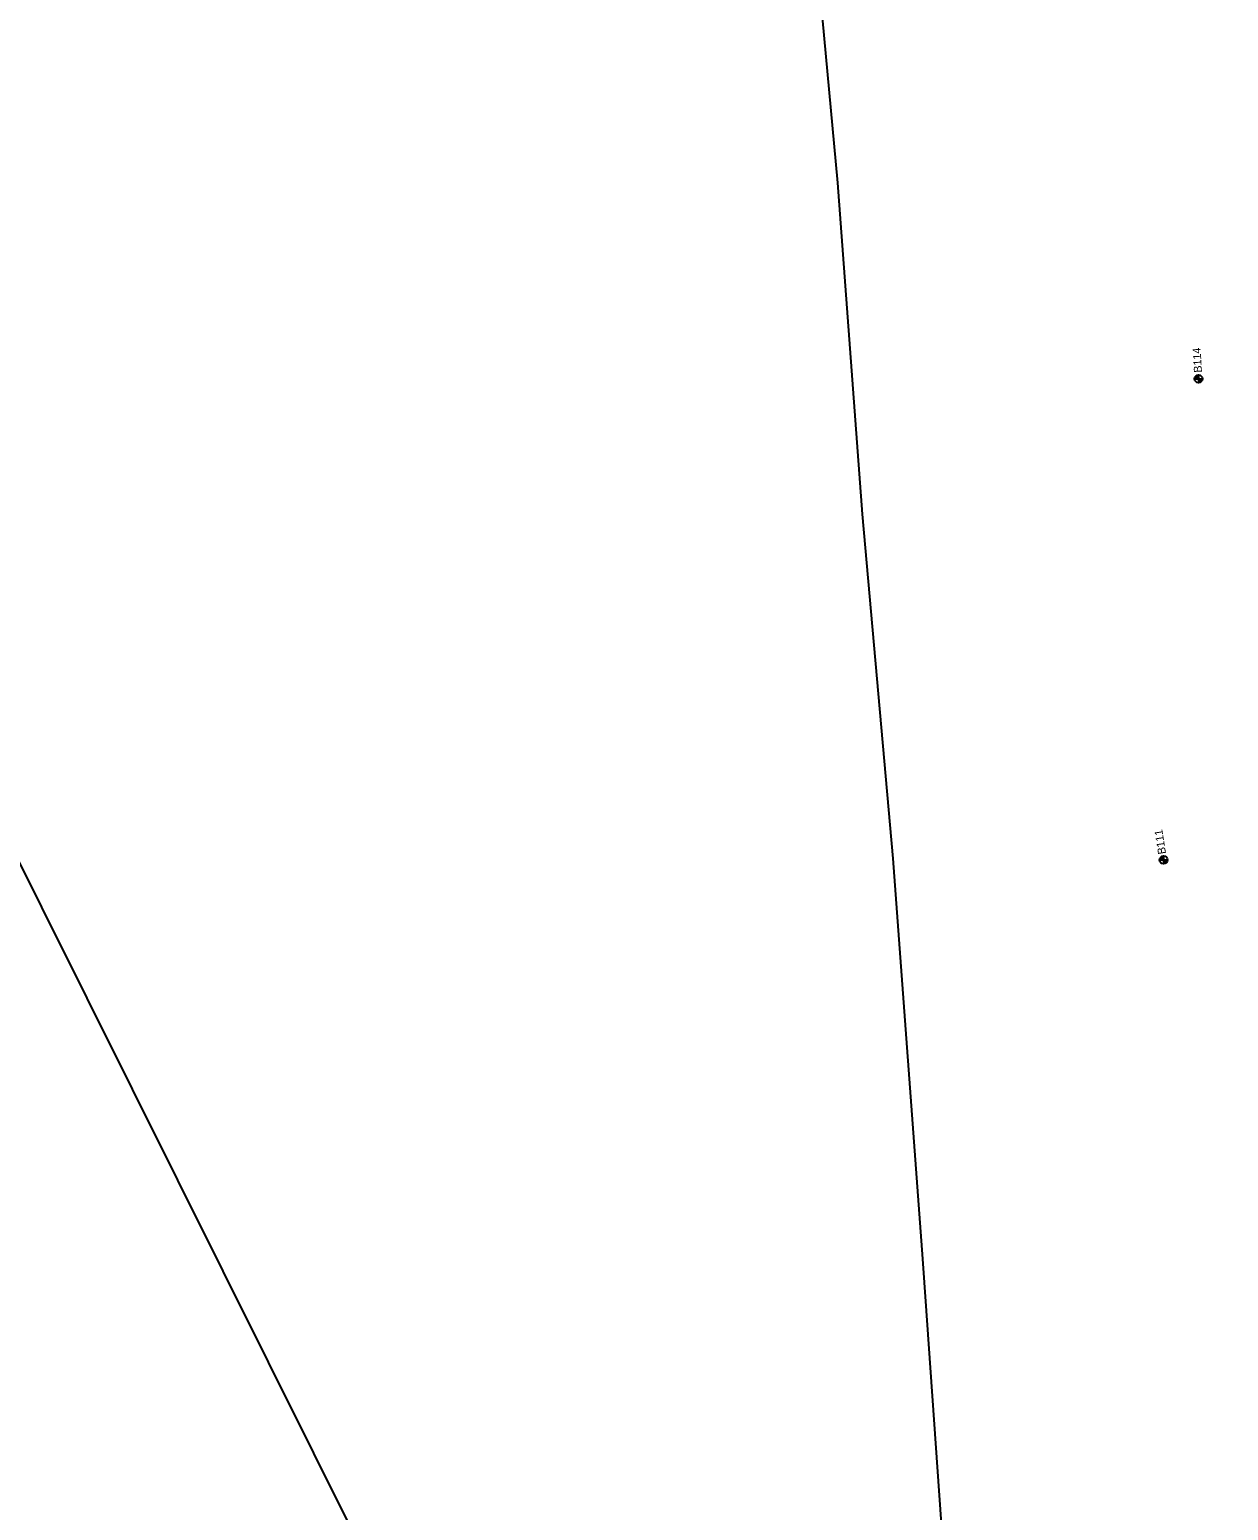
# Model space of a CAD drawing. Extents: x 345549 to 379569, y 127949 to 230467.
# Drawn here: x 353850 to 355354, y 189370 to 191230 of the extents above; entities that cross this region are included whole.
import ezdxf

# ---------------------------------------------------------------- set-up
doc = ezdxf.new("R2010")
doc.units = 0
for name, color, linetype in [('E_SOIL_BORE1 [KAPUR_CADDS_LEVELS]', 7, 'Continuous'), ('P_MARK', 7, 'Continuous'), ('P_MISC_TXT', 7, 'Continuous'), ('P_TC', 7, 'Continuous')]:
    doc.layers.add(name, color=color, linetype=linetype)

msp = doc.modelspace()

# ---------------------------------------------------------------- linework, layer by layer
at = {"layer": 'P_MARK'}
for p, q in [((355311.6, 190791.1), (355321.6, 190791.1)), ((355316.6, 190796.1), (355316.6, 190786.1)), ((355267.7, 190187.1), (355277.7, 190187.1)), ((355272.7, 190192.1), (355272.7, 190182.1))]:
    msp.add_line(p, q, dxfattribs=at)
for centre in [(355316.6, 190791.1), (355272.7, 190187.1)]:
    msp.add_circle(centre, 5, dxfattribs=at)
for centre, radius, start, end in [((355316.6, 190791.1), 4.5, 89.9869, 179.9869), ((355316.6, 190791.1), 4, 89.9869, 179.9869), ((355316.6, 190791.1), 3.5, 89.9869, 179.9869), ((355316.6, 190791.1), 3, 89.9869, 179.9869), ((355316.6, 190791.1), 2.5, 89.9869, 179.9869), ((355316.6, 190791.1), 2, 89.9869, 179.9869), ((355316.6, 190791.1), 1.5, 89.9869, 179.9869), ((355316.6, 190791.1), 1, 89.9869, 179.9869), ((355316.6, 190791.1), 0.5, 89.9869, 179.9869), ((355316.6, 190791.1), 4.5, 269.9869, 359.9869), ((355316.6, 190791.1), 4, 269.9869, 359.9869), ((355316.6, 190791.1), 3.5, 269.9869, 359.9869), ((355316.6, 190791.1), 3, 269.9869, 359.9869), ((355316.6, 190791.1), 2.5, 269.9869, 359.9869), ((355316.6, 190791.1), 2, 269.9869, 359.9869), ((355316.6, 190791.1), 1.5, 269.9869, 359.9869), ((355316.6, 190791.1), 1, 269.9869, 359.9869), ((355316.6, 190791.1), 0.5, 269.9869, 359.9869), ((355272.7, 190187.1), 4.5, 89.9869, 179.9869), ((355272.7, 190187.1), 4, 89.9869, 179.9869), ((355272.7, 190187.1), 3.5, 89.9869, 179.9869), ((355272.7, 190187.1), 3, 89.9869, 179.9869), ((355272.7, 190187.1), 2.5, 89.9869, 179.9869), ((355272.7, 190187.1), 2, 89.9869, 179.9869), ((355272.7, 190187.1), 1.5, 89.9869, 179.9869), ((355272.7, 190187.1), 1, 89.9869, 179.9869), ((355272.7, 190187.1), 0.5, 89.9869, 179.9869), ((355272.7, 190187.1), 4.5, 269.9869, 359.9869), ((355272.7, 190187.1), 4, 269.9869, 359.9869), ((355272.7, 190187.1), 3.5, 269.9869, 359.9869), ((355272.7, 190187.1), 3, 269.9869, 359.9869), ((355272.7, 190187.1), 2.5, 269.9869, 359.9869), ((355272.7, 190187.1), 2, 269.9869, 359.9869), ((355272.7, 190187.1), 1.5, 269.9869, 359.9869), ((355272.7, 190187.1), 1, 269.9869, 359.9869), ((355272.7, 190187.1), 0.5, 269.9869, 359.9869)]:
    msp.add_arc(centre, radius, start, end, dxfattribs=at)
at = {"layer": 'P_MISC_TXT'}
msp.add_line((350648.4, 196583.9), (355649.8, 186543.9), dxfattribs=at)
at = {"layer": 'P_TC'}
for points in [[(356152.8, 197292.2), (356212, 196743), (356187.3, 196360.3), (356179.9, 196244.9), (356018.8, 195710.6), (355837.4, 195262), (355656.1, 194887.8), (355482.1, 194535), (355440.2, 194457.1), (355289.7, 194177.8), (355101.7, 193774.2), (354970.8, 193454.6), (354853.6, 193071.5), (354795.4, 192718.8), (354760.1, 192236.5), (354785.6, 191878.7), (354863.4, 191037.4), (354881.9, 190789.8), (354894.4, 190621.4)], [(354894.4, 190621.4), (354933.1, 190189), (354970.1, 189686.1), (354994.6, 189341.7)]]:
    msp.add_lwpolyline(points, dxfattribs=at)

# ---------------------------------------------------------------- texts
at = {"layer": 'E_SOIL_BORE1 [KAPUR_CADDS_LEVELS]'}
for s, rotation, p in [('B114', 93.0065, (355320.9, 190799.2)), ('B111', 98.957, (355275.9, 190195))]:
    msp.add_text(s, height=10, rotation=rotation, dxfattribs=at).set_placement(p)

doc.saveas('drawing.dxf')
